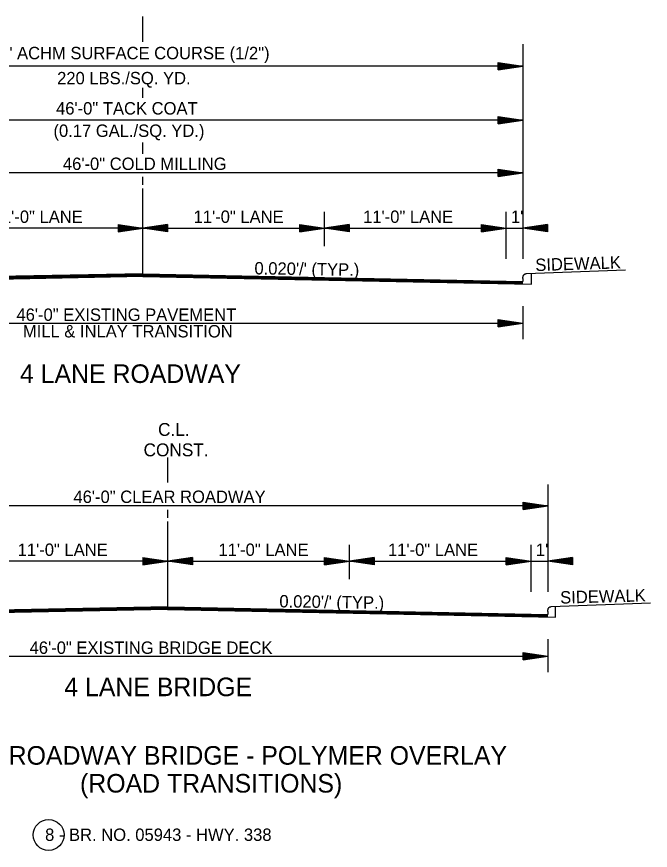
# Model space of a CAD drawing. Extents: x 544199 to 1930787, y -1968972 to 596640.
# Drawn here: x 546672 to 547056, y -1952229 to -1951724 of the extents above; entities that cross this region are included whole.
import ezdxf

# ---------------------------------------------------------------- set-up
doc = ezdxf.new("R2010")
doc.units = 0
doc.layers.add('R_Border', color=7, linetype='Continuous')
doc.layers.add('R_Draft', color=7, linetype='Continuous')

msp = doc.modelspace()

# ---------------------------------------------------------------- linework, layer by layer
at = {"layer": 'R_Border'}
for p, q in [((546748.47, -1951879.78), (546748.47, -1951828.11)), ((546748.47, -1951879.78), (546748.47, -1951828.11)), ((546980.75, -1951879.73), (547040.69, -1951877.42)), ((546983.75, -1951886.16), (546983.75, -1951879.85)), ((546763.56, -1952081.38), (546763.56, -1952029.71)), ((546763.56, -1952081.38), (546763.56, -1952029.71)), ((546995.83, -1952081.32), (547055.78, -1952079.01)), ((546998.37, -1952087.74), (546998.37, -1952081.35))]:
    msp.add_line(p, q, dxfattribs=at)
msp.add_circle((546691.42, -1952219.51), 9.34, dxfattribs=at)
for points in [[(546978.6, -1951882.72), (546978.68, -1951879.77), (546980.75, -1951879.73)], [(546993.68, -1952084.31), (546993.76, -1952081.36), (546995.83, -1952081.32)]]:
    msp.add_open_spline(points, degree=2, dxfattribs=at)
at = {"layer": 'R_Draft'}
for p, q in [((546748.47, -1951739.32), (546748.47, -1951724.16)), ((546978.6, -1951740.71), (546978.6, -1951870.84)), ((546963.6, -1951751.92), (546978.6, -1951754.17)), ((546963.6, -1951756.42), (546963.6, -1951751.92)), ((546978.6, -1951754.17), (546518.35, -1951754.17)), ((546963.6, -1951752.3), (546976.09, -1951754.17)), ((546963.6, -1951752.68), (546973.51, -1951754.17)), ((546963.6, -1951753.05), (546971.01, -1951754.17)), ((546963.6, -1951753.44), (546968.47, -1951754.17)), ((546963.6, -1951753.82), (546965.97, -1951754.17)), ((546963.6, -1951756.42), (546978.6, -1951754.17)), ((546963.6, -1951754.9), (546968.47, -1951754.17)), ((546963.6, -1951755.66), (546973.51, -1951754.17)), ((546963.6, -1951756.05), (546976.09, -1951754.17)), ((546963.6, -1951755.29), (546971.01, -1951754.17)), ((546963.6, -1951754.52), (546965.97, -1951754.17)), ((546748.47, -1951773.36), (546748.47, -1951767.25)), ((546978.6, -1951786.76), (546518.35, -1951786.76)), ((546963.6, -1951784.51), (546978.6, -1951786.76)), ((546963.6, -1951789.01), (546963.6, -1951784.51)), ((546963.6, -1951784.88), (546976.09, -1951786.76)), ((546963.6, -1951785.27), (546973.51, -1951786.76)), ((546963.6, -1951785.64), (546971.01, -1951786.76)), ((546963.6, -1951786.02), (546968.47, -1951786.76)), ((546963.6, -1951786.41), (546965.97, -1951786.76)), ((546963.6, -1951789.01), (546978.6, -1951786.76)), ((546963.6, -1951787.49), (546968.47, -1951786.76)), ((546963.6, -1951788.25), (546973.51, -1951786.76)), ((546963.6, -1951788.63), (546976.09, -1951786.76)), ((546963.6, -1951787.88), (546971.01, -1951786.76)), ((546963.6, -1951787.11), (546965.97, -1951786.76)), ((546748.47, -1951807.16), (546748.47, -1951800.25)), ((546963.6, -1951816.39), (546978.6, -1951818.64)), ((546963.6, -1951820.89), (546963.6, -1951816.39)), ((546963.6, -1951816.77), (546976.09, -1951818.64)), ((546963.6, -1951817.15), (546973.51, -1951818.64)), ((546963.6, -1951817.52), (546971.01, -1951818.64)), ((546978.6, -1951818.64), (546518.35, -1951818.64)), ((546748.47, -1951825.99), (546748.47, -1951821.06)), ((546963.6, -1951817.91), (546968.47, -1951818.64)), ((546963.6, -1951818.29), (546965.97, -1951818.64)), ((546963.6, -1951820.89), (546978.6, -1951818.64)), ((546963.6, -1951819.37), (546968.47, -1951818.64)), ((546963.6, -1951820.13), (546973.51, -1951818.64)), ((546963.6, -1951820.52), (546976.09, -1951818.64)), ((546963.6, -1951819.76), (546971.01, -1951818.64)), ((546963.6, -1951818.99), (546965.97, -1951818.64)), ((546858.47, -1951863.05), (546858.47, -1951842.29)), ((546968.47, -1951870.84), (546968.47, -1951842.29)), ((546748.47, -1951852.18), (546628.47, -1951852.18)), ((546733.47, -1951849.93), (546748.47, -1951852.18)), ((546733.47, -1951849.93), (546733.47, -1951854.43)), ((546733.47, -1951850.3), (546745.97, -1951852.18)), ((546733.47, -1951850.69), (546743.39, -1951852.18)), ((546733.47, -1951851.06), (546740.89, -1951852.18)), ((546733.47, -1951851.45), (546738.35, -1951852.18)), ((546733.47, -1951851.83), (546735.84, -1951852.18)), ((546733.47, -1951854.43), (546748.47, -1951852.18)), ((546733.47, -1951852.91), (546738.35, -1951852.18)), ((546733.47, -1951853.67), (546743.39, -1951852.18)), ((546733.47, -1951854.05), (546745.97, -1951852.18)), ((546733.47, -1951853.3), (546740.89, -1951852.18)), ((546733.47, -1951852.53), (546735.84, -1951852.18)), ((546763.47, -1951849.93), (546748.47, -1951852.18)), ((546748.47, -1951852.18), (546868.47, -1951852.18)), ((546763.47, -1951854.43), (546748.47, -1951852.18)), ((546763.47, -1951850.3), (546750.98, -1951852.18)), ((546763.47, -1951854.05), (546750.98, -1951852.18)), ((546763.47, -1951850.69), (546753.56, -1951852.18)), ((546763.47, -1951853.67), (546753.56, -1951852.18)), ((546763.47, -1951851.06), (546756.05, -1951852.18)), ((546763.47, -1951853.3), (546756.05, -1951852.18)), ((546763.47, -1951851.45), (546758.6, -1951852.18)), ((546763.47, -1951852.91), (546758.6, -1951852.18)), ((546763.47, -1951851.83), (546761.1, -1951852.18)), ((546763.47, -1951852.53), (546761.1, -1951852.18)), ((546763.47, -1951849.93), (546763.47, -1951854.43)), ((546843.47, -1951849.93), (546858.47, -1951852.18)), ((546843.47, -1951854.43), (546843.47, -1951849.93)), ((546843.47, -1951850.3), (546855.97, -1951852.18)), ((546843.47, -1951850.69), (546853.39, -1951852.18)), ((546843.47, -1951851.06), (546850.89, -1951852.18)), ((546843.47, -1951851.44), (546848.35, -1951852.18)), ((546843.47, -1951851.83), (546845.84, -1951852.18)), ((546843.47, -1951854.43), (546858.47, -1951852.18)), ((546843.47, -1951852.91), (546848.35, -1951852.18)), ((546843.47, -1951853.67), (546853.39, -1951852.18)), ((546843.47, -1951854.05), (546855.97, -1951852.18)), ((546843.47, -1951853.3), (546850.89, -1951852.18)), ((546843.47, -1951852.53), (546845.84, -1951852.18)), ((546873.47, -1951849.93), (546858.47, -1951852.18)), ((546873.47, -1951854.43), (546858.47, -1951852.18)), ((546873.47, -1951850.3), (546860.98, -1951852.18)), ((546873.47, -1951854.05), (546860.98, -1951852.18)), ((546873.47, -1951850.69), (546863.56, -1951852.18)), ((546873.47, -1951853.67), (546863.56, -1951852.18)), ((546873.47, -1951851.06), (546866.05, -1951852.18)), ((546873.47, -1951853.3), (546866.05, -1951852.18)), ((546868.47, -1951852.18), (546978.6, -1951852.18)), ((546873.47, -1951851.45), (546868.6, -1951852.18)), ((546873.47, -1951852.91), (546868.6, -1951852.18)), ((546873.47, -1951851.83), (546871.1, -1951852.18)), ((546873.47, -1951852.53), (546871.1, -1951852.18)), ((546873.47, -1951849.93), (546873.47, -1951854.43)), ((546953.47, -1951849.93), (546968.47, -1951852.18)), ((546953.47, -1951854.43), (546953.47, -1951849.93)), ((546953.47, -1951850.3), (546965.97, -1951852.18)), ((546953.47, -1951850.69), (546963.39, -1951852.18)), ((546953.47, -1951851.06), (546960.89, -1951852.18)), ((546953.47, -1951851.44), (546958.35, -1951852.18)), ((546953.47, -1951851.83), (546955.84, -1951852.18)), ((546953.47, -1951854.43), (546968.47, -1951852.18)), ((546953.47, -1951852.91), (546958.35, -1951852.18)), ((546953.47, -1951853.67), (546963.39, -1951852.18)), ((546953.47, -1951854.05), (546965.97, -1951852.18)), ((546953.47, -1951853.3), (546960.89, -1951852.18)), ((546953.47, -1951852.53), (546955.84, -1951852.18)), ((546993.6, -1951849.93), (546978.6, -1951852.18)), ((546993.6, -1951854.43), (546978.6, -1951852.18)), ((546993.6, -1951850.3), (546981.1, -1951852.18)), ((546993.6, -1951854.05), (546981.1, -1951852.18)), ((546993.6, -1951850.69), (546983.68, -1951852.18)), ((546993.6, -1951853.67), (546983.68, -1951852.18)), ((546993.6, -1951851.06), (546986.18, -1951852.18)), ((546993.6, -1951853.3), (546986.18, -1951852.18)), ((546993.6, -1951851.45), (546988.72, -1951852.18)), ((546993.6, -1951852.91), (546988.72, -1951852.18)), ((546993.6, -1951851.83), (546991.23, -1951852.18)), ((546993.6, -1951852.53), (546991.23, -1951852.18)), ((546993.6, -1951849.93), (546993.6, -1951854.43)), ((546748.5, -1951881.45), (546513.19, -1951886.16)), ((546748.47, -1951879.78), (546518.35, -1951884.39)), ((546748.48, -1951880.08), (546518.35, -1951884.69)), ((546748.48, -1951880.38), (546518.35, -1951884.99)), ((546748.49, -1951880.68), (546518.35, -1951885.29)), ((546748.49, -1951880.98), (546518.35, -1951885.59)), ((546748.5, -1951881.28), (546518.35, -1951885.89)), ((546748.44, -1951881.28), (546978.6, -1951885.89)), ((546748.44, -1951881.45), (546983.75, -1951886.16)), ((546748.45, -1951880.68), (546978.6, -1951885.29)), ((546748.45, -1951880.98), (546978.6, -1951885.59)), ((546748.46, -1951880.08), (546978.6, -1951884.69)), ((546748.46, -1951880.38), (546978.6, -1951884.99)), ((546748.47, -1951879.78), (546978.6, -1951884.39)), ((546978.6, -1951882.72), (546978.6, -1951884.39)), ((546978.6, -1951899.39), (546978.6, -1951919.39)), ((546963.6, -1951907.39), (546978.6, -1951909.64)), ((546963.6, -1951911.89), (546963.6, -1951907.39)), ((546963.6, -1951907.77), (546976.09, -1951909.64)), ((546963.6, -1951908.15), (546973.51, -1951909.64)), ((546963.6, -1951908.53), (546971.01, -1951909.64)), ((546518.35, -1951909.64), (546978.6, -1951909.64)), ((546963.6, -1951908.91), (546968.47, -1951909.64)), ((546963.6, -1951909.29), (546965.97, -1951909.64)), ((546963.6, -1951911.89), (546978.6, -1951909.64)), ((546963.6, -1951910.37), (546968.47, -1951909.64)), ((546963.6, -1951911.14), (546973.51, -1951909.64)), ((546963.6, -1951911.52), (546976.09, -1951909.64)), ((546963.6, -1951910.76), (546971.01, -1951909.64)), ((546963.6, -1951910), (546965.97, -1951909.64)), ((546763.56, -1952006.21), (546763.56, -1951991.05)), ((546993.68, -1952007.37), (546993.68, -1952072.43)), ((546978.68, -1952017.98), (546993.68, -1952020.23)), ((546978.68, -1952022.48), (546978.68, -1952017.98)), ((546978.68, -1952018.36), (546991.18, -1952020.23)), ((546978.68, -1952018.74), (546988.6, -1952020.23)), ((546978.68, -1952019.12), (546986.1, -1952020.23)), ((546978.68, -1952019.5), (546983.56, -1952020.23)), ((546993.68, -1952020.23), (546533.43, -1952020.23)), ((546763.56, -1952027.59), (546763.56, -1952022.65)), ((546978.68, -1952019.88), (546981.05, -1952020.23)), ((546978.68, -1952022.48), (546993.68, -1952020.23)), ((546978.68, -1952020.96), (546983.56, -1952020.23)), ((546978.68, -1952021.73), (546988.6, -1952020.23)), ((546978.68, -1952022.11), (546991.18, -1952020.23)), ((546978.68, -1952021.35), (546986.1, -1952020.23)), ((546978.68, -1952020.59), (546981.05, -1952020.23)), ((546873.56, -1952064.65), (546873.56, -1952043.88)), ((546983.56, -1952072.43), (546983.56, -1952043.88)), ((546763.56, -1952053.77), (546643.56, -1952053.77)), ((546748.56, -1952051.52), (546763.56, -1952053.77)), ((546748.56, -1952051.52), (546748.56, -1952056.02)), ((546748.56, -1952051.9), (546761.05, -1952053.77)), ((546748.56, -1952052.28), (546758.47, -1952053.77)), ((546748.56, -1952052.65), (546755.97, -1952053.77)), ((546748.56, -1952053.04), (546753.43, -1952053.77)), ((546748.56, -1952053.42), (546750.93, -1952053.77)), ((546748.56, -1952056.02), (546763.56, -1952053.77)), ((546748.56, -1952054.51), (546753.43, -1952053.77)), ((546748.56, -1952055.26), (546758.47, -1952053.77)), ((546748.56, -1952055.65), (546761.05, -1952053.77)), ((546748.56, -1952054.89), (546755.97, -1952053.77)), ((546748.56, -1952054.12), (546750.93, -1952053.77)), ((546778.56, -1952051.52), (546763.56, -1952053.77)), ((546763.56, -1952053.77), (546883.56, -1952053.77)), ((546778.56, -1952056.02), (546763.56, -1952053.77)), ((546778.56, -1952051.9), (546766.06, -1952053.77)), ((546778.56, -1952055.65), (546766.06, -1952053.77)), ((546778.56, -1952052.28), (546768.64, -1952053.77)), ((546778.56, -1952055.26), (546768.64, -1952053.77)), ((546778.56, -1952052.65), (546771.14, -1952053.77)), ((546778.56, -1952054.89), (546771.14, -1952053.77)), ((546778.56, -1952053.04), (546773.68, -1952053.77)), ((546778.56, -1952054.51), (546773.68, -1952053.77)), ((546778.56, -1952053.42), (546776.19, -1952053.77)), ((546778.56, -1952054.12), (546776.19, -1952053.77)), ((546778.56, -1952051.52), (546778.56, -1952056.02)), ((546858.56, -1952051.52), (546873.56, -1952053.77)), ((546858.56, -1952056.02), (546858.56, -1952051.52)), ((546858.56, -1952051.9), (546871.05, -1952053.77)), ((546858.56, -1952052.28), (546868.47, -1952053.77)), ((546858.56, -1952052.65), (546865.97, -1952053.77)), ((546858.56, -1952053.04), (546863.43, -1952053.77)), ((546858.56, -1952053.42), (546860.93, -1952053.77)), ((546858.56, -1952056.02), (546873.56, -1952053.77)), ((546858.56, -1952054.5), (546863.43, -1952053.77)), ((546858.56, -1952055.26), (546868.47, -1952053.77)), ((546858.56, -1952055.65), (546871.05, -1952053.77)), ((546858.56, -1952054.89), (546865.97, -1952053.77)), ((546858.56, -1952054.12), (546860.93, -1952053.77)), ((546888.56, -1952051.52), (546873.56, -1952053.77)), ((546888.56, -1952056.02), (546873.56, -1952053.77)), ((546888.56, -1952051.9), (546876.06, -1952053.77)), ((546888.56, -1952055.65), (546876.06, -1952053.77)), ((546888.56, -1952052.28), (546878.64, -1952053.77)), ((546888.56, -1952055.26), (546878.64, -1952053.77)), ((546888.56, -1952052.65), (546881.14, -1952053.77)), ((546888.56, -1952054.89), (546881.14, -1952053.77)), ((546883.56, -1952053.77), (546993.68, -1952053.77)), ((546888.56, -1952053.04), (546883.68, -1952053.77)), ((546888.56, -1952054.51), (546883.68, -1952053.77)), ((546888.56, -1952053.42), (546886.19, -1952053.77)), ((546888.56, -1952054.12), (546886.19, -1952053.77)), ((546888.56, -1952051.52), (546888.56, -1952056.02)), ((546968.56, -1952051.52), (546983.56, -1952053.77)), ((546968.56, -1952056.02), (546968.56, -1952051.52)), ((546968.56, -1952051.9), (546981.05, -1952053.77)), ((546968.56, -1952052.28), (546978.47, -1952053.77)), ((546968.56, -1952052.65), (546975.97, -1952053.77)), ((546968.56, -1952053.04), (546973.43, -1952053.77)), ((546968.56, -1952053.42), (546970.93, -1952053.77)), ((546968.56, -1952056.02), (546983.56, -1952053.77)), ((546968.56, -1952054.5), (546973.43, -1952053.77)), ((546968.56, -1952055.26), (546978.47, -1952053.77)), ((546968.56, -1952055.65), (546981.05, -1952053.77)), ((546968.56, -1952054.89), (546975.97, -1952053.77)), ((546968.56, -1952054.12), (546970.93, -1952053.77)), ((547008.68, -1952051.52), (546993.68, -1952053.77)), ((547008.68, -1952056.02), (546993.68, -1952053.77)), ((547008.68, -1952051.9), (546996.19, -1952053.77)), ((547008.68, -1952055.65), (546996.19, -1952053.77)), ((547008.68, -1952052.28), (546998.77, -1952053.77)), ((547008.68, -1952055.26), (546998.77, -1952053.77)), ((547008.68, -1952052.65), (547001.26, -1952053.77)), ((547008.68, -1952054.89), (547001.26, -1952053.77)), ((547008.68, -1952053.04), (547003.81, -1952053.77)), ((547008.68, -1952054.51), (547003.81, -1952053.77)), ((547008.68, -1952053.42), (547006.31, -1952053.77)), ((547008.68, -1952054.12), (547006.31, -1952053.77)), ((547008.68, -1952051.52), (547008.68, -1952056.02)), ((546763.59, -1952083.05), (546528.15, -1952087.76)), ((546763.56, -1952081.38), (546533.43, -1952085.98)), ((546763.56, -1952081.68), (546533.43, -1952086.28)), ((546763.57, -1952081.98), (546533.43, -1952086.58)), ((546763.57, -1952082.28), (546533.43, -1952086.88)), ((546763.58, -1952082.58), (546533.43, -1952087.18)), ((546763.59, -1952082.88), (546533.43, -1952087.48)), ((546763.52, -1952083.05), (546998.37, -1952087.74)), ((546763.53, -1952082.58), (546993.68, -1952087.18)), ((546763.53, -1952082.88), (546993.68, -1952087.48)), ((546763.54, -1952081.98), (546993.68, -1952086.58)), ((546763.54, -1952082.28), (546993.68, -1952086.88)), ((546763.55, -1952081.68), (546993.68, -1952086.28)), ((546763.56, -1952081.38), (546993.68, -1952085.98)), ((546993.68, -1952084.31), (546993.68, -1952085.98)), ((546993.68, -1952100.99), (546993.68, -1952120.99)), ((546978.68, -1952108.99), (546993.68, -1952111.24)), ((546978.68, -1952113.49), (546978.68, -1952108.99)), ((546978.68, -1952109.36), (546991.18, -1952111.24)), ((546978.68, -1952109.74), (546988.6, -1952111.24)), ((546978.68, -1952110.12), (546986.1, -1952111.24)), ((546533.43, -1952111.24), (546993.68, -1952111.24)), ((546978.68, -1952110.5), (546983.56, -1952111.24)), ((546978.68, -1952110.88), (546981.05, -1952111.24)), ((546978.68, -1952113.49), (546993.68, -1952111.24)), ((546978.68, -1952111.96), (546983.56, -1952111.24)), ((546978.68, -1952112.73), (546988.6, -1952111.24)), ((546978.68, -1952113.11), (546991.18, -1952111.24)), ((546978.68, -1952112.35), (546986.1, -1952111.24)), ((546978.68, -1952111.59), (546981.05, -1952111.24))]:
    msp.add_line(p, q, dxfattribs=at)

# ---------------------------------------------------------------- texts
for s, height, p in [('46\'-0" ACHM SURFACE COURSE (1/2")', 7.5, (546644, -1951749.93)), ('220 LBS./SQ. YD. ', 7.5, (546696.59, -1951765.11)), ('46\'-0" TACK COAT', 7.5, (546695.94, -1951783.4)), ('(0.17 GAL./SQ. YD.)', 7.5, (546694.38, -1951796.95)), ('46\'-0" COLD MILLING', 7.5, (546700.09, -1951816.97)), ('11\'-0" LANE', 7.5, (546657.61, -1951849.01)), ('11\'-0" LANE', 7.5, (546779.21, -1951849.01)), ('11\'-0" LANE', 7.5, (546881.87, -1951849.01)), ("1'", 7.5, (546971.39, -1951849.01)), ('46\'-0" EXISTING PAVEMENT', 7.5, (546671.96, -1951908.32)), ('MILL & INLAY TRANSITION', 7.5, (546675.86, -1951918.35)), ('4 LANE ROADWAY', 11.25, (546674.1, -1951945.9)), ('C.L.', 7.8, (546757.71, -1951977.96)), ('CONST.', 7.8, (546748.93, -1951990.32)), ('46\'-0" CLEAR ROADWAY ', 7.5, (546706.47, -1952018.56)), ('11\'-0" LANE', 7.5, (546672.7, -1952050.6)), ('11\'-0" LANE', 7.5, (546794.3, -1952050.6)), ('11\'-0" LANE', 7.5, (546896.95, -1952050.6)), ("1'", 7.5, (546986.47, -1952050.6)), ('46\'-0" EXISTING BRIDGE DECK', 7.5, (546679.93, -1952109.91)), ('4 LANE BRIDGE ', 11.25, (546700.93, -1952135.52)), ('46 FT. CLEAR ROADWAY BRIDGE - POLYMER OVERLAY', 11.25, (546565.26, -1952177.01)), ('(ROAD TRANSITIONS)', 11.25, (546710.45, -1952193.88)), ('8 - BR. NO. 05943 - HWY. 338', 7.5, (546689.31, -1952223.14))]:
    msp.add_text(s, height=height, dxfattribs=at).set_placement(p)
for s, rotation, p in [("0.020'/' (TYP.)", 359.1281, (546816.03, -1951880.15)), ('SIDEWALK', 1.8639, (546986.25, -1951878.23)), ("0.020'/' (TYP.)", 359.1281, (546831.12, -1952081.74)), ('SIDEWALK', 1.4961, (547001.27, -1952079.51))]:
    msp.add_text(s, height=7.5, rotation=rotation, dxfattribs=at).set_placement(p)

doc.saveas('drawing.dxf')
